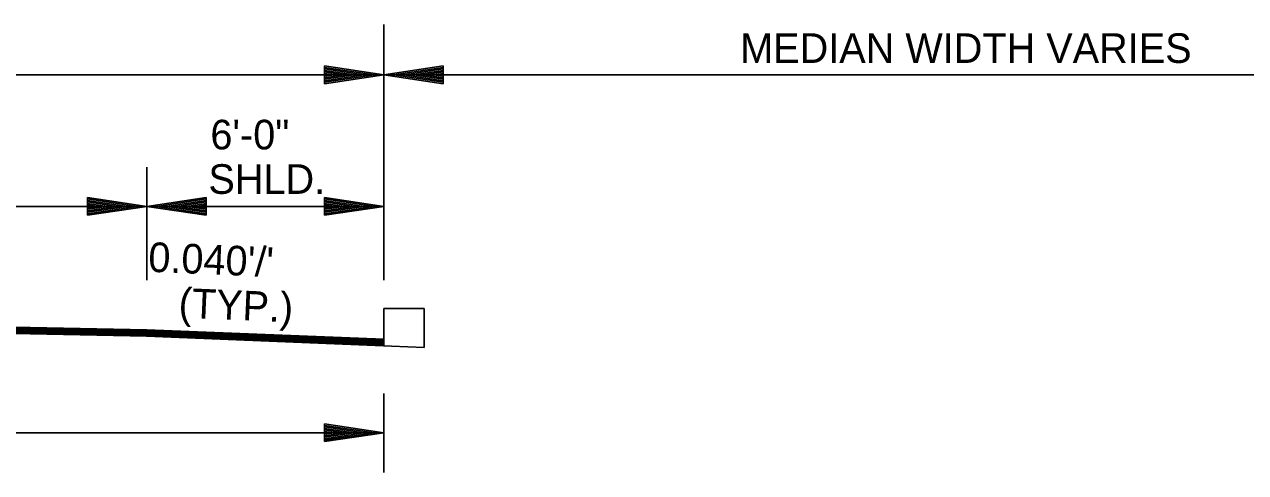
# Model space of a CAD drawing. Extents: x 542112 to 1930787, y -1968972 to 596640.
# Drawn here: x 544703.6 to 545012.5, y -1950147.6 to -1950034.2 of the extents above; entities that cross this region are included whole.
import ezdxf

# ---------------------------------------------------------------- set-up
doc = ezdxf.new("R2010")
doc.units = 0
doc.layers.add('R_Border', color=7, linetype='Continuous')
doc.layers.add('R_Draft', color=7, linetype='Continuous')

msp = doc.modelspace()

# ---------------------------------------------------------------- linework, layer by layer
at = {"layer": 'R_Border'}
for p, q in [((544794.54, -1950115.53), (544794.54, -1950106.13)), ((544794.54, -1950106.13), (544804.71, -1950106.13)), ((544804.71, -1950106.13), (544804.71, -1950115.94))]:
    msp.add_line(p, q, dxfattribs=at)
at = {"layer": 'R_Draft'}
for p, q in [((544794.54, -1950034.21), (544794.54, -1950098.92)), ((544779.54, -1950044.72), (544794.54, -1950046.97)), ((544779.54, -1950044.72), (544779.54, -1950049.22)), ((544809.54, -1950044.72), (544794.54, -1950046.97)), ((544809.54, -1950044.72), (544809.54, -1950049.22)), ((544314.54, -1950046.97), (544794.54, -1950046.97)), ((544779.54, -1950045.09), (544792.04, -1950046.97)), ((544779.54, -1950045.47), (544789.46, -1950046.97)), ((544779.54, -1950045.85), (544786.96, -1950046.97)), ((544779.54, -1950046.24), (544784.42, -1950046.97)), ((544779.54, -1950046.61), (544781.91, -1950046.97)), ((544779.54, -1950049.22), (544794.54, -1950046.97)), ((544779.54, -1950047.7), (544784.42, -1950046.97)), ((544779.54, -1950048.46), (544789.46, -1950046.97)), ((544779.54, -1950048.84), (544792.04, -1950046.97)), ((544779.54, -1950048.08), (544786.96, -1950046.97)), ((544779.54, -1950047.32), (544781.91, -1950046.97)), ((544809.54, -1950049.22), (544794.54, -1950046.97)), ((545094.54, -1950046.97), (544794.54, -1950046.97)), ((544809.54, -1950045.09), (544797.05, -1950046.97)), ((544809.54, -1950048.84), (544797.05, -1950046.97)), ((544809.54, -1950045.47), (544799.63, -1950046.97)), ((544809.54, -1950048.46), (544799.63, -1950046.97)), ((544809.54, -1950045.85), (544802.12, -1950046.97)), ((544809.54, -1950048.08), (544802.12, -1950046.97)), ((544809.54, -1950046.24), (544804.67, -1950046.97)), ((544809.54, -1950047.7), (544804.67, -1950046.97)), ((544809.54, -1950046.61), (544807.17, -1950046.97)), ((544809.54, -1950047.32), (544807.17, -1950046.97)), ((544734.54, -1950098.92), (544734.54, -1950070.37)), ((544719.54, -1950078.01), (544734.54, -1950080.26)), ((544719.54, -1950078.01), (544719.54, -1950082.51)), ((544719.54, -1950078.39), (544732.04, -1950080.26)), ((544719.54, -1950078.77), (544729.46, -1950080.26)), ((544749.54, -1950078.01), (544734.54, -1950080.26)), ((544749.54, -1950078.39), (544737.05, -1950080.26)), ((544749.54, -1950078.77), (544739.63, -1950080.26)), ((544749.54, -1950078.01), (544749.54, -1950082.51)), ((544779.54, -1950078.01), (544794.54, -1950080.26)), ((544779.54, -1950078.01), (544779.54, -1950082.51)), ((544779.54, -1950078.39), (544792.04, -1950080.26)), ((544779.54, -1950078.77), (544789.46, -1950080.26)), ((544614.54, -1950080.26), (544734.54, -1950080.26)), ((544719.54, -1950079.14), (544726.96, -1950080.26)), ((544719.54, -1950079.53), (544724.42, -1950080.26)), ((544719.54, -1950079.91), (544721.91, -1950080.26)), ((544719.54, -1950082.51), (544734.54, -1950080.26)), ((544719.54, -1950081), (544724.42, -1950080.26)), ((544719.54, -1950081.75), (544729.46, -1950080.26)), ((544719.54, -1950082.14), (544732.04, -1950080.26)), ((544719.54, -1950081.38), (544726.96, -1950080.26)), ((544719.54, -1950080.61), (544721.91, -1950080.26)), ((544734.54, -1950080.26), (544794.54, -1950080.26)), ((544749.54, -1950082.51), (544734.54, -1950080.26)), ((544749.54, -1950082.14), (544737.05, -1950080.26)), ((544749.54, -1950081.75), (544739.63, -1950080.26)), ((544749.54, -1950079.14), (544742.12, -1950080.26)), ((544749.54, -1950081.38), (544742.12, -1950080.26)), ((544749.54, -1950079.53), (544744.67, -1950080.26)), ((544749.54, -1950081), (544744.67, -1950080.26)), ((544749.54, -1950079.91), (544747.17, -1950080.26)), ((544749.54, -1950080.61), (544747.17, -1950080.26)), ((544779.54, -1950079.14), (544786.96, -1950080.26)), ((544779.54, -1950079.53), (544784.42, -1950080.26)), ((544779.54, -1950079.91), (544781.91, -1950080.26)), ((544779.54, -1950082.51), (544794.54, -1950080.26)), ((544779.54, -1950081), (544784.42, -1950080.26)), ((544779.54, -1950081.75), (544789.46, -1950080.26)), ((544779.54, -1950082.14), (544792.04, -1950080.26)), ((544779.54, -1950081.38), (544786.96, -1950080.26)), ((544779.54, -1950080.61), (544781.91, -1950080.26)), ((544554.54, -1950107.87), (544734.54, -1950111.47)), ((544554.54, -1950108.17), (544734.54, -1950111.77)), ((544554.54, -1950108.47), (544734.54, -1950112.07)), ((544554.54, -1950108.77), (544734.54, -1950112.37)), ((544554.54, -1950109.07), (544734.54, -1950112.67)), ((544554.54, -1950109.37), (544734.54, -1950112.97)), ((544554.54, -1950109.53), (544734.54, -1950113.13)), ((544734.5, -1950112.97), (544794.54, -1950115.37)), ((544734.51, -1950112.67), (544794.54, -1950115.07)), ((544734.52, -1950112.07), (544794.54, -1950114.47)), ((544734.52, -1950112.37), (544794.54, -1950114.77)), ((544734.53, -1950111.77), (544794.54, -1950114.17)), ((544734.54, -1950111.47), (544794.54, -1950113.87)), ((544734.48, -1950113.13), (544804.71, -1950115.94)), ((544794.54, -1950127.63), (544794.54, -1950147.63)), ((544314.54, -1950137.55), (544794.54, -1950137.55)), ((544779.54, -1950135.3), (544794.54, -1950137.55)), ((544779.54, -1950135.3), (544779.54, -1950139.8)), ((544779.54, -1950135.68), (544792.04, -1950137.55)), ((544779.54, -1950136.06), (544789.46, -1950137.55)), ((544779.54, -1950136.44), (544786.96, -1950137.55)), ((544779.54, -1950136.83), (544784.42, -1950137.55)), ((544779.54, -1950137.2), (544781.91, -1950137.55)), ((544779.54, -1950139.8), (544794.54, -1950137.55)), ((544779.54, -1950138.29), (544784.42, -1950137.55)), ((544779.54, -1950139.05), (544789.46, -1950137.55)), ((544779.54, -1950139.43), (544792.04, -1950137.55)), ((544779.54, -1950138.67), (544786.96, -1950137.55)), ((544779.54, -1950137.91), (544781.91, -1950137.55))]:
    msp.add_line(p, q, dxfattribs=at)

# ---------------------------------------------------------------- texts
for s, p in [('MEDIAN WIDTH VARIES', (544884.66, -1950043.95)), ('6\'-0" ', (544750.63, -1950065.84)), ('SHLD.', (544750.13, -1950077.09))]:
    msp.add_text(s, height=7.5, dxfattribs=at).set_placement(p)
for s, p in [("  0.040'/'", (544729.24, -1950096.55)), (' (TYP.)', (544739.7, -1950108.26))]:
    msp.add_text(s, height=7.5, rotation=357.552, dxfattribs=at).set_placement(p)

doc.saveas('drawing.dxf')
